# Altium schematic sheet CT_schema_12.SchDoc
size 385 x 278 mm
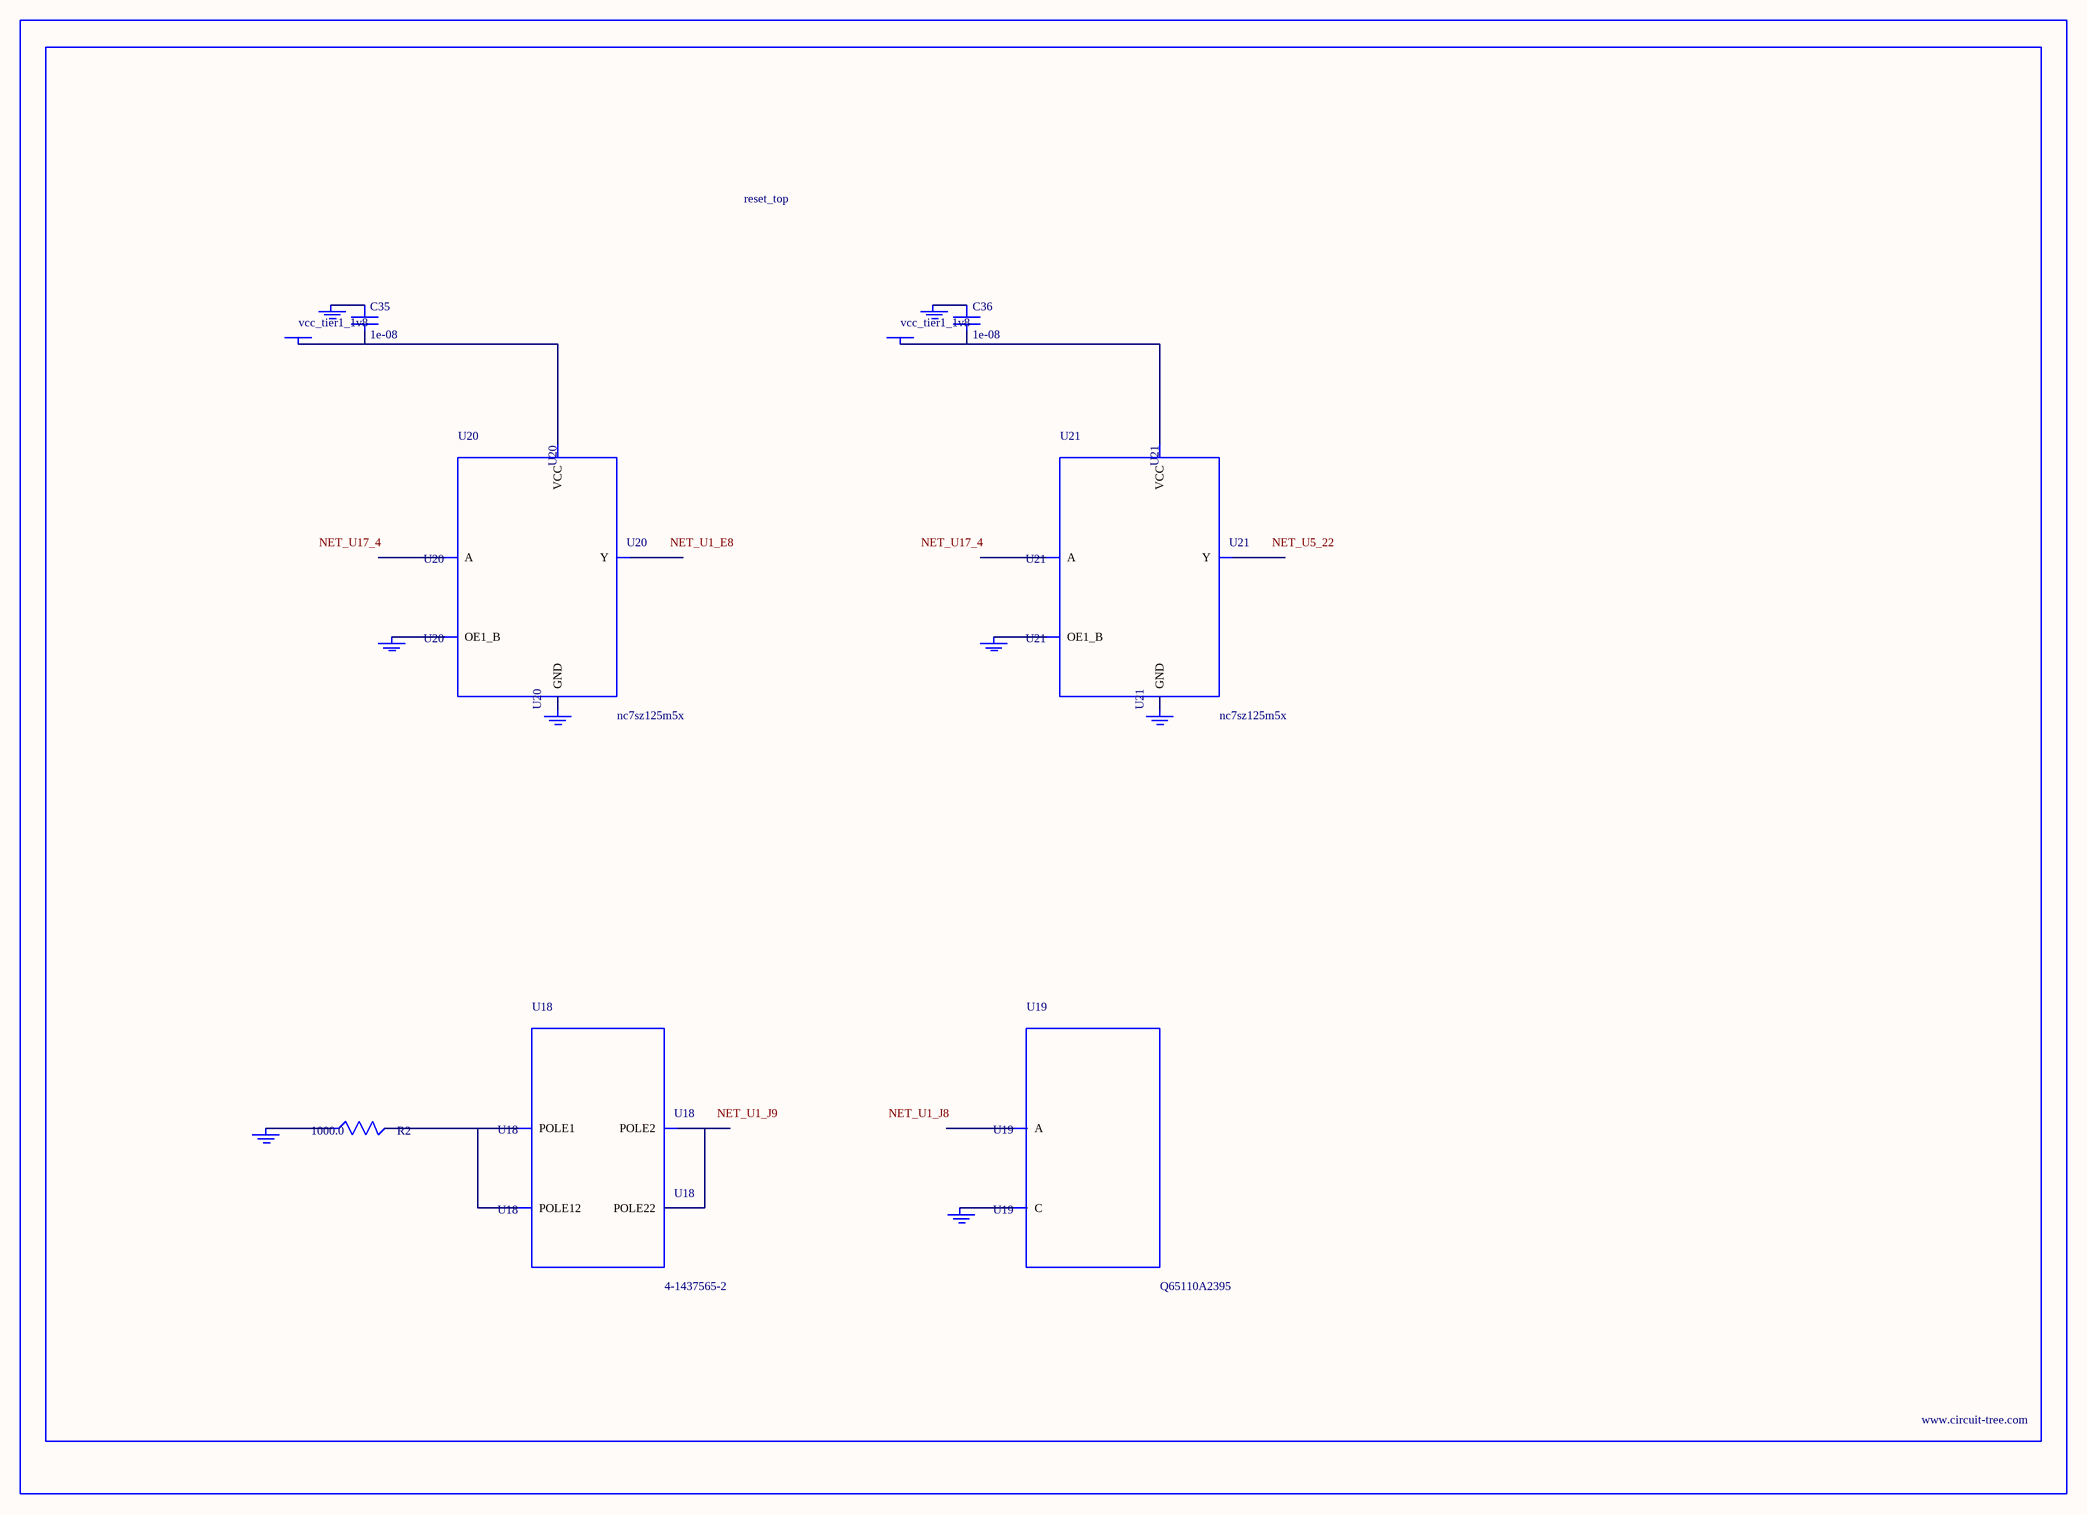
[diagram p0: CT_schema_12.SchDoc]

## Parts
BORDER11  (no value)
C35  1e-08  [C0402]
C36  1e-08  [C0402]
GND_INSTANCE_11_0  (no value)
GND_INSTANCE_11_1  (no value)
GND_INSTANCE_11_2  (no value)
GND_INSTANCE_11_3  (no value)
GND_INSTANCE_11_4  (no value)
GND_INSTANCE_11_5  (no value)
GND_INSTANCE_11_6  (no value)
GND_INSTANCE_11_7  (no value)
POWER_INSTANCE_11_0  vcc_tier1_1v8
POWER_INSTANCE_11_1  vcc_tier1_1v8
R2  1000.0  [R0603]
U18  4-1437565-2  [SW_4-1437565-2]
U19  Q65110A2395  [LGM67K-G1J2-24-Z]
U20  nc7sz125m5x  [NC7SZ125M5X]
U21  nc7sz125m5x  [NC7SZ125M5X]

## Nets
NetC35_1: C35.1 GND_INSTANCE_11_2.0(GND)
NetC35_2: C35.2 POWER_INSTANCE_11_0.0(PWR) U20.5(VCC)
NetC36_1: C36.1 GND_INSTANCE_11_5.0(GND)
NetC36_2: C36.2 POWER_INSTANCE_11_1.0(PWR) U21.5(VCC)
NetGND_INSTANCE_11_0_0: GND_INSTANCE_11_0.0(GND) R2.1
NetGND_INSTANCE_11_1_0: GND_INSTANCE_11_1.0(GND) U19.C
NetGND_INSTANCE_11_3_0: GND_INSTANCE_11_3.0(GND) U20.1(OE1_B)
NetGND_INSTANCE_11_4_0: GND_INSTANCE_11_4.0(GND) U20.3(GND)
NetGND_INSTANCE_11_6_0: GND_INSTANCE_11_6.0(GND) U21.1(OE1_B)
NetGND_INSTANCE_11_7_0: GND_INSTANCE_11_7.0(GND) U21.3(GND)
NetR2_2: R2.2 U18.1(POLE1) U18.2(POLE12)
NetU18_3: U18.3(POLE2) U18.4(POLE22)

Not connected (* = marked no-connect by the designer): U19 A; U20 2(A) 4(Y); U21 2(A) 4(Y)

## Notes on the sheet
- Labels drawn without touching a wire or pin: NET_U1_E8, NET_U1_J8, NET_U1_J9, NET_U5_22, NET_U17_4

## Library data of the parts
BORDER11 = BORDER_PAGE11
C35 C36 = C0402C103K3RAC
GND_INSTANCE_11_0-GND_INSTANCE_11_7 = GND
POWER_INSTANCE_11_0 POWER_INSTANCE_11_1 = PWR
R2 = RC0603JR-071KL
